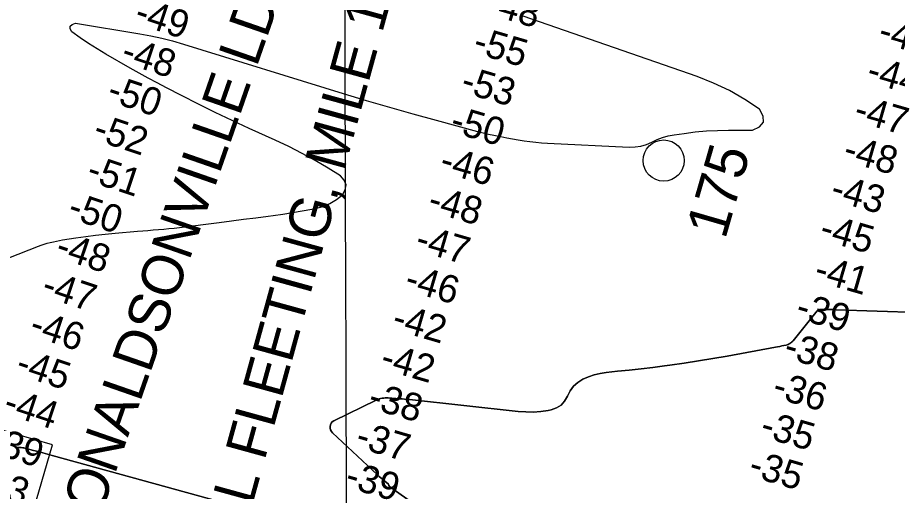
# Model space of a CAD drawing. Extents: x 3361039 to 3398939, y 576572 to 602007.
# Drawn here: x 3390699 to 3392837, y 585353 to 586504 of the extents above; entities that cross this region are included whole.
import ezdxf

# ---------------------------------------------------------------- set-up
doc = ezdxf.new("R2010")
doc.units = 0
for name, color, linetype in [('V-CHAN-NAID', 7, 'Continuous'), ('V-GRID-MAJR', 7, 'Continuous'), ('V-RIVR-EDGE', 7, 'Continuous'), ('V-RIVR-IDEN', 7, 'Continuous'), ('V-RIVR-MILE', 7, 'Continuous'), ('V-RIVR-RANG', 7, 'Continuous'), ('V-RRAP-RVMT', 7, 'Continuous'), ('V-TOPO-DPTH', 7, 'Continuous'), ('V-TOPO-GNAM-IDEN', 7, 'Continuous'), ('V-TOPO-MAJR', 7, 'Continuous'), ('V-TOPO-MINR', 7, 'Continuous')]:
    doc.layers.add(name, color=color, linetype=linetype)

msp = doc.modelspace()

# ---------------------------------------------------------------- linework, layer by layer
at = {"layer": 'V-GRID-MAJR'}
msp.add_spline([(3391508.2, 582029.8), (3391489.7, 588089), (3391471.2, 594150.1), (3391452.7, 600211.2), (3391452.7, 600213.1)], degree=3, dxfattribs=at)
at = {"layer": 'V-RIVR-EDGE'}
msp.add_spline([(3387368.6, 585771), (3387389, 585767.6), (3387407.3, 585766.1), (3387418.2, 585761.7), (3387425.5, 585756.5), (3387441.6, 585752.8), (3387452.6, 585751.4), (3387462.1, 585753.9), (3387477.4, 585758.2), (3387482.9, 585759.3), (3387491.7, 585759.3), (3387502.3, 585758.2), (3387510.3, 585756.3), (3387521.6, 585753), (3387530.1, 585752.3), (3387538.5, 585752.2), (3387549.8, 585752.2), (3387558.9, 585755.5), (3387571.4, 585756.9), (3387583.4, 585757.3), (3387598.4, 585756.1), (3387629.8, 585749.5), (3387659.8, 585743.5), (3387703.3, 585736.8), (3387727.4, 585734.2), (3387739.1, 585733.5), (3387750.8, 585734.2), (3387753.7, 585731.6), (3387763.2, 585723.9), (3387774.5, 585720.6), (3387790.6, 585719.8), (3387800.1, 585721.6), (3387814, 585720.1), (3387824.6, 585720.1), (3387847.3, 585714.2), (3387884.2, 585709.4), (3387930.2, 585702.7), (3387980.6, 585701.1), (3388035.1, 585696.5), (3388076, 585694.6), (3388096.9, 585693.8), (3388120.3, 585690.5), (3388145.1, 585685.3), (3388171.8, 585682.3), (3388198.8, 585676.8), (3388222.6, 585669.4), (3388245.6, 585660.6), (3388260.9, 585655.4), (3388279.6, 585655.4), (3388291.3, 585658.3), (3388298.9, 585663.7), (3388299.3, 585666.3), (3388299, 585670.7), (3388290.6, 585674.4), (3388291.7, 585677.3), (3388293.9, 585678.4), (3388303, 585677.6), (3388318.7, 585676.5), (3388334.1, 585672.8), (3388354.1, 585663.6), (3388357.1, 585659.9), (3388363.3, 585658.1), (3388368.4, 585658.1), (3388371, 585661), (3388375.3, 585662.1), (3388379, 585661.3), (3388383, 585659.1), (3388383.7, 585654.4), (3388384.1, 585649.3), (3388389.9, 585647.4), (3388406, 585642.3), (3388468.9, 585637.7), (3388491.5, 585635.8), (3388534.6, 585628.4), (3388578.1, 585619.2), (3388610.6, 585613.6), (3388635.9, 585612.1), (3388727.9, 585599.4), (3388768.5, 585591.7), (3388822.6, 585580.9), (3388865, 585570.6), (3388906.6, 585562.8), (3388924.1, 585559.5), (3388938.8, 585562), (3388961.4, 585563.4), (3388974.2, 585560.1), (3389007.5, 585553.4), (3389018.8, 585554.5), (3389027.2, 585555.9), (3389037.1, 585555.9), (3389051.7, 585553.7), (3389061.2, 585553.3), (3389081.3, 585552.1), (3389098.1, 585551), (3389120.4, 585548.7), (3389143.4, 585546.5), (3389160.2, 585542.1), (3389200.8, 585534.7), (3389222.3, 585525.1), (3389247.2, 585519.2), (3389280.4, 585509.6), (3389307.5, 585497.8), (3389334.5, 585487.2), (3389349.5, 585483.1), (3389361.5, 585483.1), (3389382.7, 585479), (3389397, 585476.8), (3389416.7, 585468.7), (3389441.9, 585458.4), (3389464.9, 585451.4), (3389479.5, 585449.2), (3389506.2, 585446.2), (3389533.2, 585447.2), (3389558.5, 585444.2), (3389577.8, 585437.9), (3389603.4, 585431.3), (3389618.7, 585425.1), (3389639.2, 585415.1), (3389657.8, 585410.3), (3389693.2, 585404.8), (3389768.9, 585383), (3389806.5, 585373), (3389854.3, 585362.3), (3389881.7, 585358.6), (3389913.9, 585354.5), (3389953.7, 585349.3), (3390008.2, 585341.8), (3390037.8, 585336.3), (3390074.3, 585327.8), (3390128, 585312.7), (3390164.5, 585301.6), (3390200.7, 585289.8), (3390292.7, 585255.6), (3390327.1, 585241.3), (3390360.7, 585231.7), (3390404.5, 585221), (3390454.9, 585214.3), (3390483.1, 585210.5), (3390491.8, 585209.4), (3390494.4, 585207.2), (3390501.3, 585201), (3390507.9, 585200.6), (3390527.3, 585196.2), (3390545.9, 585195), (3390557.6, 585194.3), (3390574.4, 585189.8), (3390605.5, 585179.5), (3390698.6, 585148.2), (3390763.2, 585126.9), (3390811.1, 585111), (3390852.4, 585097.8), (3390900.9, 585081.6), (3390948.1, 585063.5), (3390993.7, 585048.4), (3391036.8, 585031.9), (3391070.8, 585020.1), (3391140.5, 584997.6), (3391201.5, 584974.1), (3391247.5, 584957.5), (3391310.7, 584933.6), (3391362.2, 584914.8), (3391400.6, 584900.1), (3391441.8, 584885.7), (3391505.4, 584861.1), (3391563.5, 584841.9), (3391658.8, 584807.3), (3391712.8, 584786), (3391758.8, 584767.3), (3391796.1, 584749.6), (3391880.4, 584718.3), (3391926.8, 584701.4), (3391969.2, 584685.2), (3392003.9, 584666.9), (3392040, 584650.3), (3392077.6, 584636), (3392135.7, 584613.2), (3392164.9, 584598.1), (3392196, 584583.8), (3392224.8, 584578.2), (3392263.5, 584567.9), (3392290.6, 584559.8), (3392322.7, 584546.5), (3392396.5, 584512.7), (3392439.9, 584496.2), (3392471.7, 584484.8), (3392502, 584473.3), (3392510.8, 584467.5), (3392535.2, 584458.3), (3392606.1, 584432.9), (3392632.4, 584421.5), (3392666.7, 584406.8), (3392715.6, 584386.9), (3392777.4, 584364.8), (3392827, 584348.3), (3392863.6, 584335.4), (3392897.9, 584321.8), (3392928.6, 584307.8), (3392965.4, 584294.9), (3393010, 584279.1), (3393054.6, 584263.2), (3393092.5, 584248.5), (3393195.2, 584206.6), (3393234.2, 584187.9), (3393264.5, 584173.5), (3393294.1, 584162.1), (3393336.8, 584147.4), (3393374.5, 584136.3), (3393402.2, 584127.5), (3393414.3, 584119.8), (3393435.4, 584109.1), (3393459.2, 584098.1), (3393478.9, 584087.5), (3393513.6, 584076.4), (3393541.7, 584067.2), (3393588.1, 584047.4), (3393643.2, 584028.9), (3393668.4, 584018.3), (3393699.8, 584005), (3393737.1, 583991.8), (3393781.7, 583976), (3393884.7, 583943.2), (3393927, 583928.8), (3393981.1, 583908.2), (3394043.9, 583885.4), (3394095.8, 583868.1), (3394154.9, 583847.1), (3394200.2, 583830.5), (3394247, 583816.2), (3394293, 583801.4), (3394349.6, 583781.2), (3394409.1, 583754.7), (3394451.8, 583730.5), (3394470.5, 583720.2), (3394481.8, 583715.4), (3394494.2, 583713.6), (3394502.6, 583708.1), (3394507.3, 583700.4), (3394511.3, 583697.8), (3394522.7, 583692.3), (3394557.3, 583675.8), (3394600.4, 583659.9), (3394658.1, 583638.9), (3394704.5, 583623.5), (3394760.4, 583607.6), (3394824, 583588.8), (3394867.8, 583570.8), (3394925.9, 583546.9), (3394972.2, 583528.9), (3394995.6, 583520), (3395064.7, 583504.2), (3395088.4, 583499.3), (3395120.2, 583491.6), (3395149.1, 583480.5), (3395173.2, 583476.8), (3395201.3, 583471.3), (3395236.4, 583459.9), (3395256.8, 583451.8), (3395280.9, 583445.5), (3395300.3, 583445.1), (3395316.7, 583440.7), (3395324.4, 583433.3), (3395335.3, 583426), (3395353.6, 583417.9), (3395398.9, 583403.9), (3395426.3, 583397.2), (3395442, 583391), (3395455.9, 583383.3), (3395476, 583377.8), (3395495.7, 583369.3), (3395511, 583368.2), (3395530.4, 583365.9), (3395550.5, 583361.8), (3395654.6, 583334.9), (3395704.7, 583322.4), (3395743.7, 583306.9), (3395765.3, 583295.5), (3395788.3, 583286.3), (3395816.4, 583278.9), (3395861.7, 583270.8), (3395916.2, 583261.5), (3395960.7, 583252.6), (3396008.6, 583242.6), (3396060.8, 583230.5), (3396093.4, 583222.3), (3396135.4, 583208.7), (3396170.1, 583199.8), (3396204.4, 583191.3), (3396254.8, 583177.3), (3396301.2, 583165.9), (3396364.4, 583152.9), (3396399.1, 583144.4), (3396426.9, 583138.5), (3396463.1, 583133), (3396489.8, 583132.9), (3396523.4, 583130.2), (3396607.8, 583114), (3396670.3, 583102.1), (3396708.3, 583095.4), (3396743, 583089.5), (3396775.1, 583083.9)], degree=3, dxfattribs=at)
at = {"layer": 'V-RIVR-MILE'}
msp.add_circle((3392268.7, 586156.5), 50, dxfattribs=at)
at = {"layer": 'V-RRAP-RVMT'}
msp.add_lwpolyline([(3390685.7, 585129), (3390783.7, 585465.6), (3390648.8, 585504.8), (3390652.2, 585515.7), (3390497.3, 585563.3), (3390495.9, 585558.8), (3390372.4, 585595.5), (3390373.7, 585599.7), (3390218.6, 585646.7), (3390217.1, 585641.8), (3390080.1, 585682.4), (3390078.7, 585677.7), (3389945.1, 585716.3), (3389952.9, 585741.6), (3389804, 585787.6), (3389799.7, 585774.2), (3389655.5, 585815.8), (3389654.5, 585812.6)], dxfattribs=at)
at = {"layer": 'V-TOPO-DPTH'}
for points in [[(3392887.4, 585787.2), (3392688.1, 585794), (3392682.6, 585794.2), (3392677, 585794.3), (3392671.4, 585794.4), (3392665.8, 585794.5), (3392649.3, 585794.7), (3392647, 585794.4), (3392642.9, 585792.5), (3392641.3, 585790.9), (3392583.3, 585718.7), (3392581.6, 585716.8), (3392579.7, 585715), (3392577.7, 585713.5), (3392575.6, 585712), (3392573.3, 585710.8), (3392570.9, 585709.8), (3392568.5, 585708.9), (3392566, 585708.2), (3392560.9, 585707), (3392555.8, 585705.9), (3392550.7, 585704.8), (3392545.6, 585703.7), (3392540.5, 585702.8), (3392422.8, 585681.3), (3392388.1, 585675.2), (3392353.4, 585669.5), (3392318.6, 585664.2), (3392283.7, 585659.4), (3392270.9, 585657.7), (3392242.4, 585654), (3392213.8, 585650.6), (3392185.1, 585647.4), (3392156.5, 585644.3), (3392129, 585641.5), (3392114.3, 585639.2), (3392099.9, 585635.9), (3392086, 585631), (3392072.3, 585625.1), (3392072.1, 585625.1), (3392060.1, 585617.2), (3392049.6, 585608), (3392041.5, 585596.7), (3392034.8, 585584), (3392027.9, 585572), (3392019.2, 585562.1), (3392007.9, 585555.4), (3391994.9, 585550.7), (3391988.1, 585549.4), (3391970, 585546.9), (3391951.8, 585545.4), (3391933.6, 585545.5), (3391915.4, 585546.7), (3391651, 585575.6), (3391644.9, 585576.2), (3391638.9, 585576.8), (3391632.8, 585577.3), (3391626.7, 585577.7), (3391599.5, 585579.5), (3391595.7, 585579.6), (3391591.9, 585579.6), (3391588.2, 585579.3), (3391584.4, 585578.8), (3391580.7, 585578.1), (3391577, 585577.1), (3391573.5, 585575.8), (3391570, 585574.3), (3391466.8, 585523.7), (3391463.3, 585521.3), (3391460.5, 585518.3), (3391458.9, 585514.6), (3391457.9, 585510.5), (3391458.2, 585506.1), (3391459.2, 585502.1), (3391461.3, 585498.4), (3391464, 585495), (3391573.1, 585393.1), (3391577.5, 585389), (3391582, 585385), (3391586.6, 585381.1), (3391591.2, 585377.2), (3391599.7, 585370.3), (3391600.3, 585369.4), (3391600.5, 585367.2), (3391602.7, 585364.3), (3391604.6, 585362.6), (3391605.6, 585361.8), (3391833.3, 585200.8)], [(3391833.3, 585200.8), (3391605.6, 585361.8), (3391604.6, 585362.6), (3391602.7, 585364.3), (3391600.5, 585367.2), (3391600.3, 585369.4), (3391599.7, 585370.3), (3391591.2, 585377.2), (3391586.6, 585381.1), (3391582, 585385), (3391577.5, 585389), (3391573.1, 585393.1), (3391464, 585495), (3391461.3, 585498.4), (3391459.2, 585502.1), (3391458.2, 585506.1), (3391457.9, 585510.5), (3391458.9, 585514.6), (3391460.5, 585518.3), (3391463.3, 585521.3), (3391466.8, 585523.7), (3391570, 585574.3), (3391573.5, 585575.8), (3391577, 585577.1), (3391580.7, 585578.1), (3391584.4, 585578.8), (3391588.2, 585579.3), (3391591.9, 585579.6), (3391595.7, 585579.6), (3391599.5, 585579.5), (3391626.7, 585577.7), (3391632.8, 585577.3), (3391638.9, 585576.8), (3391644.9, 585576.2), (3391651, 585575.6), (3391915.4, 585546.7), (3391933.6, 585545.5), (3391951.8, 585545.4), (3391970, 585546.9), (3391988.1, 585549.4), (3391994.9, 585550.7), (3392007.9, 585555.4), (3392019.2, 585562.1), (3392027.9, 585572), (3392034.8, 585584), (3392041.5, 585596.7), (3392049.6, 585608), (3392060.1, 585617.2), (3392072.1, 585625.1), (3392072.3, 585625.1), (3392086, 585631), (3392099.9, 585635.9), (3392114.3, 585639.2), (3392129, 585641.5), (3392156.5, 585644.3), (3392185.1, 585647.4), (3392213.8, 585650.6), (3392242.4, 585654), (3392270.9, 585657.7), (3392283.7, 585659.4), (3392318.6, 585664.2), (3392353.4, 585669.5), (3392388.1, 585675.2), (3392422.8, 585681.3), (3392540.5, 585702.8), (3392545.6, 585703.7), (3392550.7, 585704.8), (3392555.8, 585705.9), (3392560.9, 585707), (3392566, 585708.2), (3392568.5, 585708.9), (3392570.9, 585709.8), (3392573.3, 585710.8), (3392575.6, 585712), (3392577.7, 585713.5), (3392579.7, 585715), (3392581.6, 585716.8), (3392583.3, 585718.7), (3392641.3, 585790.9), (3392642.9, 585792.5), (3392647, 585794.4), (3392649.3, 585794.7), (3392665.8, 585794.5), (3392671.4, 585794.4), (3392677, 585794.3), (3392682.6, 585794.2), (3392688.1, 585794), (3392887.4, 585787.2)], [(3391491.5, 585244.6), (3390782.9, 585439.8), (3390771.4, 585442.9), (3390759.9, 585446.1), (3390748.4, 585449.2), (3390736.9, 585452.2), (3390716.2, 585457.7), (3390713.9, 585458.3), (3390711.5, 585458.6), (3390707.5, 585459), (3390706.2, 585459.2), (3390703.5, 585459.3), (3390700.8, 585459.2), (3390696.7, 585459.3)], [(3390696.7, 585459.3), (3390700.8, 585459.2), (3390703.5, 585459.3), (3390706.2, 585459.2), (3390707.5, 585459), (3390711.5, 585458.6), (3390713.9, 585458.3), (3390716.2, 585457.7), (3390736.9, 585452.2), (3390748.4, 585449.2), (3390759.9, 585446.1), (3390771.4, 585442.9), (3390782.9, 585439.8), (3391491.5, 585244.6)]]:
    msp.add_lwpolyline(points, dxfattribs=at)
at = {"layer": 'V-TOPO-MAJR'}
msp.add_lwpolyline([(3390677.5, 585920.3), (3390749, 585948.5), (3390756.1, 585951.2), (3390763.3, 585953.6), (3390770.6, 585955.7), (3390778, 585957.7), (3390785.4, 585959.3), (3390792.9, 585960.9), (3390800.4, 585962.2), (3390807.9, 585963.5), (3390840.3, 585968.4), (3390864.1, 585971.8), (3390887.9, 585974.9), (3390911.7, 585977.6), (3390935.6, 585979.9), (3390990, 585984.8), (3391002.7, 585985.9), (3391015.4, 585986.9), (3391028.1, 585987.9), (3391040.9, 585988.9), (3391053.6, 585989.9), (3391066.3, 585991.1), (3391078.9, 585992.4), (3391091.6, 585993.9), (3391188.4, 586006.1), (3391218.1, 586009.9), (3391247.8, 586013.7), (3391277.5, 586017.6), (3391307.2, 586021.5), (3391319.4, 586023.1), (3391343, 586026.4), (3391366.5, 586029.9), (3391390, 586033.9), (3391413.4, 586038.1), (3391422.7, 586039.8), (3391440.7, 586044.9), (3391457.7, 586051.8), (3391473.3, 586061.6), (3391487.9, 586073.3), (3391494.6, 586085.7), (3391496.8, 586097.6), (3391492.2, 586108.9), (3391483, 586119.6), (3391453.3, 586137.9), (3391421.8, 586156.4), (3391389.9, 586174), (3391357.4, 586190.5), (3391324.4, 586206.1), (3391261.7, 586234.3), (3391220.1, 586253.4), (3391178.8, 586273.1), (3391137.8, 586293.4), (3391097, 586314.2), (3391060.3, 586333.3), (3391038.1, 586345), (3391016.1, 586356.9), (3390994.2, 586369), (3390972.3, 586381.3), (3390913.3, 586415.1), (3390892, 586427.7), (3390871, 586440.9), (3390850.5, 586454.7), (3390830.2, 586469), (3390826.6, 586476.8), (3390826.3, 586483.2), (3390831.1, 586487.4), (3390839.2, 586490.3), (3390995.3, 586464.6), (3391022.1, 586459.6), (3391048.8, 586453.9), (3391075.2, 586447.1), (3391101.4, 586439.6), (3391489.5, 586319.7), (3391545.9, 586302.6), (3391602.4, 586285.9), (3391659.1, 586269.8), (3391715.9, 586254.2), (3391816.3, 586227), (3391823, 586225.3), (3391829.7, 586223.6), (3391836.4, 586222.1), (3391843.1, 586220.7), (3391873, 586214.6), (3391887.1, 586211.8), (3391901.2, 586209.2), (3391915.3, 586206.9), (3391929.4, 586204.6), (3391943.6, 586202.8), (3391957.8, 586201.1), (3391972, 586199.9), (3391986.3, 586199), (3392185.2, 586189.1), (3392199.4, 586189.6), (3392213.3, 586191.5), (3392226.6, 586195.7), (3392239.7, 586201.4), (3392252.7, 586207.5), (3392266, 586212.6), (3392279.8, 586216.4), (3392293.9, 586219.1), (3392318.7, 586222.6), (3392345.5, 586225.9), (3392372.4, 586228.3), (3392399.3, 586229.6), (3392426.3, 586230.2), (3392484.7, 586230.2), (3392501.8, 586238.7), (3392511.5, 586249.6), (3392510.1, 586264.1), (3392501.3, 586281.1), (3392465.5, 586304.8), (3392428.6, 586326.3), (3392389.8, 586344.4), (3392349.9, 586360.3), (3391927.4, 586506.9)], dxfattribs=at)
at = {"layer": 'V-TOPO-MINR'}
for points in [[(3392887.4, 585787.2), (3392688.1, 585794), (3392682.6, 585794.2), (3392677, 585794.3), (3392671.4, 585794.4), (3392665.8, 585794.5), (3392649.3, 585794.7), (3392647, 585794.4), (3392642.9, 585792.5), (3392641.3, 585790.9), (3392583.3, 585718.7), (3392581.6, 585716.8), (3392579.7, 585715), (3392577.7, 585713.5), (3392575.6, 585712), (3392573.3, 585710.8), (3392570.9, 585709.8), (3392568.5, 585708.9), (3392566, 585708.2), (3392560.9, 585707), (3392555.8, 585705.9), (3392550.7, 585704.8), (3392545.6, 585703.7), (3392540.5, 585702.8), (3392422.8, 585681.3), (3392388.1, 585675.2), (3392353.4, 585669.5), (3392318.6, 585664.2), (3392283.7, 585659.4), (3392270.9, 585657.7), (3392242.4, 585654), (3392213.8, 585650.6), (3392185.1, 585647.4), (3392156.5, 585644.3), (3392129, 585641.5), (3392114.3, 585639.2), (3392099.9, 585635.9), (3392086, 585631), (3392072.3, 585625.1), (3392072.1, 585625.1), (3392060.1, 585617.2), (3392049.6, 585608), (3392041.5, 585596.7), (3392034.8, 585584), (3392027.9, 585572), (3392019.2, 585562.1), (3392007.9, 585555.4), (3391994.9, 585550.7), (3391988.1, 585549.4), (3391970, 585546.9), (3391951.8, 585545.4), (3391933.6, 585545.5), (3391915.4, 585546.7), (3391651, 585575.6), (3391644.9, 585576.2), (3391638.9, 585576.8), (3391632.8, 585577.3), (3391626.7, 585577.7), (3391599.5, 585579.5), (3391595.7, 585579.6), (3391591.9, 585579.6), (3391588.2, 585579.3), (3391584.4, 585578.8), (3391580.7, 585578.1), (3391577, 585577.1), (3391573.5, 585575.8), (3391570, 585574.3), (3391466.8, 585523.7), (3391463.3, 585521.3), (3391460.5, 585518.3), (3391458.9, 585514.6), (3391457.9, 585510.5), (3391458.2, 585506.1), (3391459.2, 585502.1), (3391461.3, 585498.4), (3391464, 585495), (3391573.1, 585393.1), (3391577.5, 585389), (3391582, 585385), (3391586.6, 585381.1), (3391591.2, 585377.2), (3391599.7, 585370.3), (3391600.3, 585369.4), (3391600.5, 585367.2), (3391602.7, 585364.3), (3391604.6, 585362.6), (3391605.6, 585361.8), (3391833.3, 585200.8)], [(3391491.5, 585244.6), (3390782.9, 585439.8), (3390771.4, 585442.9), (3390759.9, 585446.1), (3390748.4, 585449.2), (3390736.9, 585452.2), (3390716.2, 585457.7), (3390713.9, 585458.3), (3390711.5, 585458.6), (3390707.5, 585459), (3390706.2, 585459.2), (3390703.5, 585459.3), (3390700.8, 585459.2), (3390696.7, 585459.3)]]:
    msp.add_lwpolyline(points, dxfattribs=at)

# ---------------------------------------------------------------- texts
at = {"layer": 'V-CHAN-NAID'}
msp.add_text('L & L FLEETING, MILE 175 (176.0) (2)', height=100, rotation=74.6237, dxfattribs=at).set_placement((3391205.9, 585088.5))
at = {"layer": 'V-RIVR-IDEN'}
msp.add_text('175', height=100, rotation=73.8907, dxfattribs=at).set_placement((3392418, 585962.9))
at = {"layer": 'V-RIVR-RANG'}
for s, rotation, p in [('-48', 343.702, (3391833.3, 586514.3)), ('-49', 341.5598, (3390979, 586491.7)), ('-49', 343.8157, (3392786.3, 586445)), ('-55', 343.702, (3391802, 586419.3)), ('-48', 341.5598, (3390946.4, 586397.1)), ('-44', 343.8157, (3392758.2, 586349)), ('-53', 343.702, (3391772.2, 586323.8)), ('-50', 341.5598, (3390912.3, 586303.1)), ('-47', 343.8157, (3392727.3, 586253.9)), ('-50', 343.702, (3391746.2, 586227.3)), ('-52', 341.5598, (3390878.6, 586208.9)), ('-48', 343.8157, (3392701.2, 586157.3)), ('-51', 341.5598, (3390862.5, 586108.9)), ('-46', 343.702, (3391720.6, 586130.5)), ('-43', 343.8157, (3392670.5, 586062.1)), ('-48', 343.702, (3391691.8, 586034.8)), ('-50', 341.5598, (3390816.7, 586018.7)), ('-45', 343.8157, (3392643.9, 585965.7)), ('-47', 343.702, (3391661.5, 585939.4)), ('-48', 341.5598, (3390787.1, 585923.2)), ('-41', 343.8157, (3392630.8, 585865.4)), ('-46', 343.702, (3391635.7, 585842.8)), ('-47', 341.5598, (3390753.2, 585829.1)), ('-39', 343.8157, (3392586, 585774.3)), ('-46', 341.5598, (3390723.8, 585733.5)), ('-42', 343.702, (3391604.9, 585747.6)), ('-38', 343.8157, (3392557.1, 585678.5)), ('-42', 343.702, (3391576.6, 585651.7)), ('-45', 341.5598, (3390690.5, 585639.2)), ('-36', 343.8157, (3392529.5, 585582.4)), ('-38', 343.702, (3391546.8, 585556.2)), ('-44', 341.5598, (3390660.3, 585543.8)), ('-35', 343.8157, (3392499.9, 585486.9)), ('-39', 341.5598, (3390625, 585450.2)), ('-37', 343.702, (3391516.5, 585460.9)), ('-35', 343.8157, (3392471.7, 585390.9)), ('-39', 343.702, (3391490.9, 585364.2)), ('-33', 341.5598, (3390589.8, 585356.5))]:
    msp.add_text(s, height=67, rotation=rotation, dxfattribs=at).set_placement(p)
at = {"layer": 'V-TOPO-GNAM-IDEN'}
msp.add_text('DONALDSONVILLE LDG.', height=100, rotation=70.8012, dxfattribs=at).set_placement((3390868.7, 585202.3))

doc.saveas('drawing.dxf')
